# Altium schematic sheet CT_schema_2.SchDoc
size 199 x 169 mm
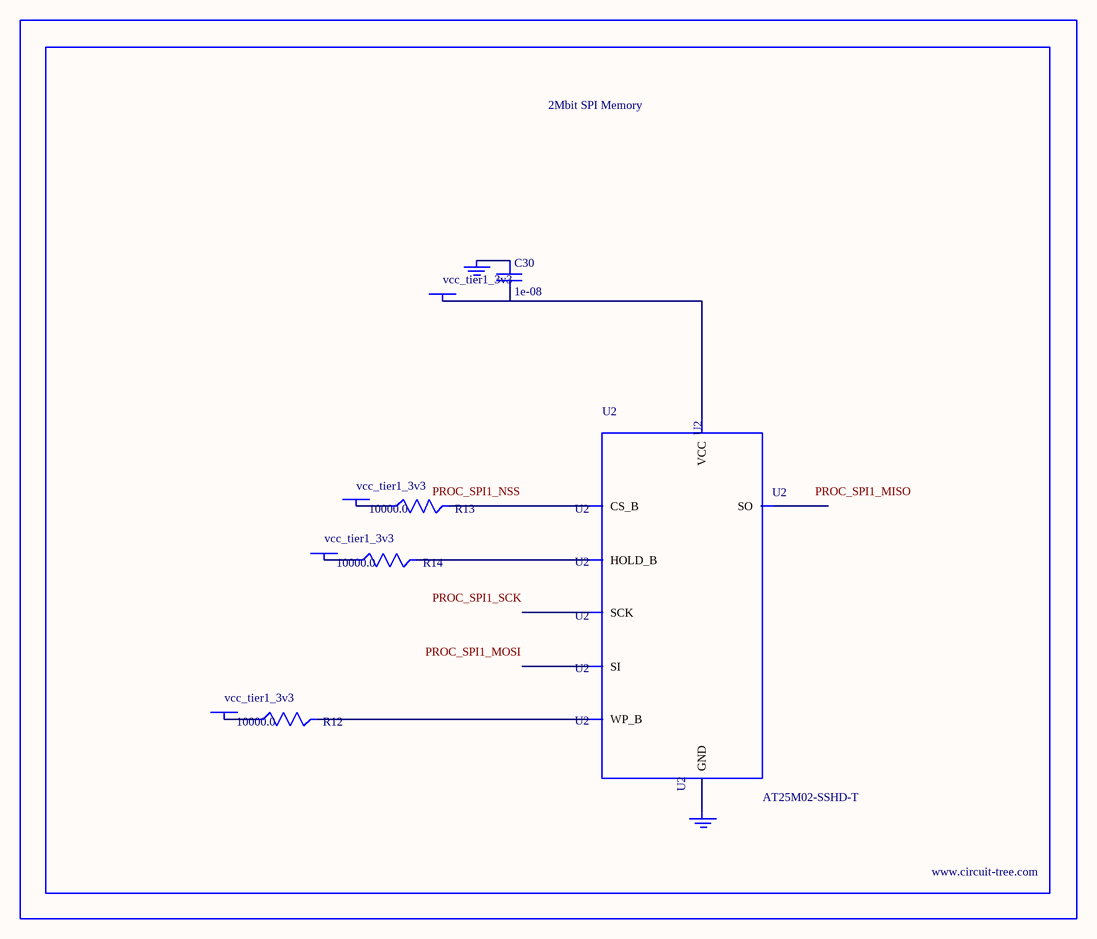
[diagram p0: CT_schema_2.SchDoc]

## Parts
BORDER1  (no value)
C30  1e-08  [C0402]
GND_INSTANCE_1_0  (no value)
GND_INSTANCE_1_1  (no value)
POWER_INSTANCE_1_0  vcc_tier1_3v3
POWER_INSTANCE_1_1  vcc_tier1_3v3
POWER_INSTANCE_1_2  vcc_tier1_3v3
POWER_INSTANCE_1_3  vcc_tier1_3v3
R12  10000.0  [R0603]
R13  10000.0  [R0603]
R14  10000.0  [R0603]
U2  AT25M02-SSHD-T  [SOIC-8]

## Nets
NetC30_1: C30.1 GND_INSTANCE_1_0.0(GND)
NetC30_2: C30.2 POWER_INSTANCE_1_3.0(PWR) U2.8(VCC)
NetGND_INSTANCE_1_1_0: GND_INSTANCE_1_1.0(GND) U2.4(GND)
NetPOWER_INSTANCE_1_0_0: POWER_INSTANCE_1_0.0(PWR) R13.1
NetPOWER_INSTANCE_1_1_0: POWER_INSTANCE_1_1.0(PWR) R12.1
NetPOWER_INSTANCE_1_2_0: POWER_INSTANCE_1_2.0(PWR) R14.1
NetR12_2: R12.2 U2.3(WP_B)
NetR13_2: R13.2 U2.1(CS_B)
NetR14_2: R14.2 U2.7(HOLD_B)

Not connected (* = marked no-connect by the designer): U2 2(SO) 5(SI) 6(SCK)

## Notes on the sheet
- Labels drawn without touching a wire or pin: PROC_SPI1_MISO, PROC_SPI1_MOSI, PROC_SPI1_NSS, PROC_SPI1_SCK

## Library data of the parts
BORDER1 = BORDER_PAGE1
C30 = C0402C103K3RAC
GND_INSTANCE_1_0 GND_INSTANCE_1_1 = GND
POWER_INSTANCE_1_0-POWER_INSTANCE_1_3 = PWR
R12-R14 = RC0603JR-0710KL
